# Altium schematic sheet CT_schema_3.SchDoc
size 590 x 495 mm
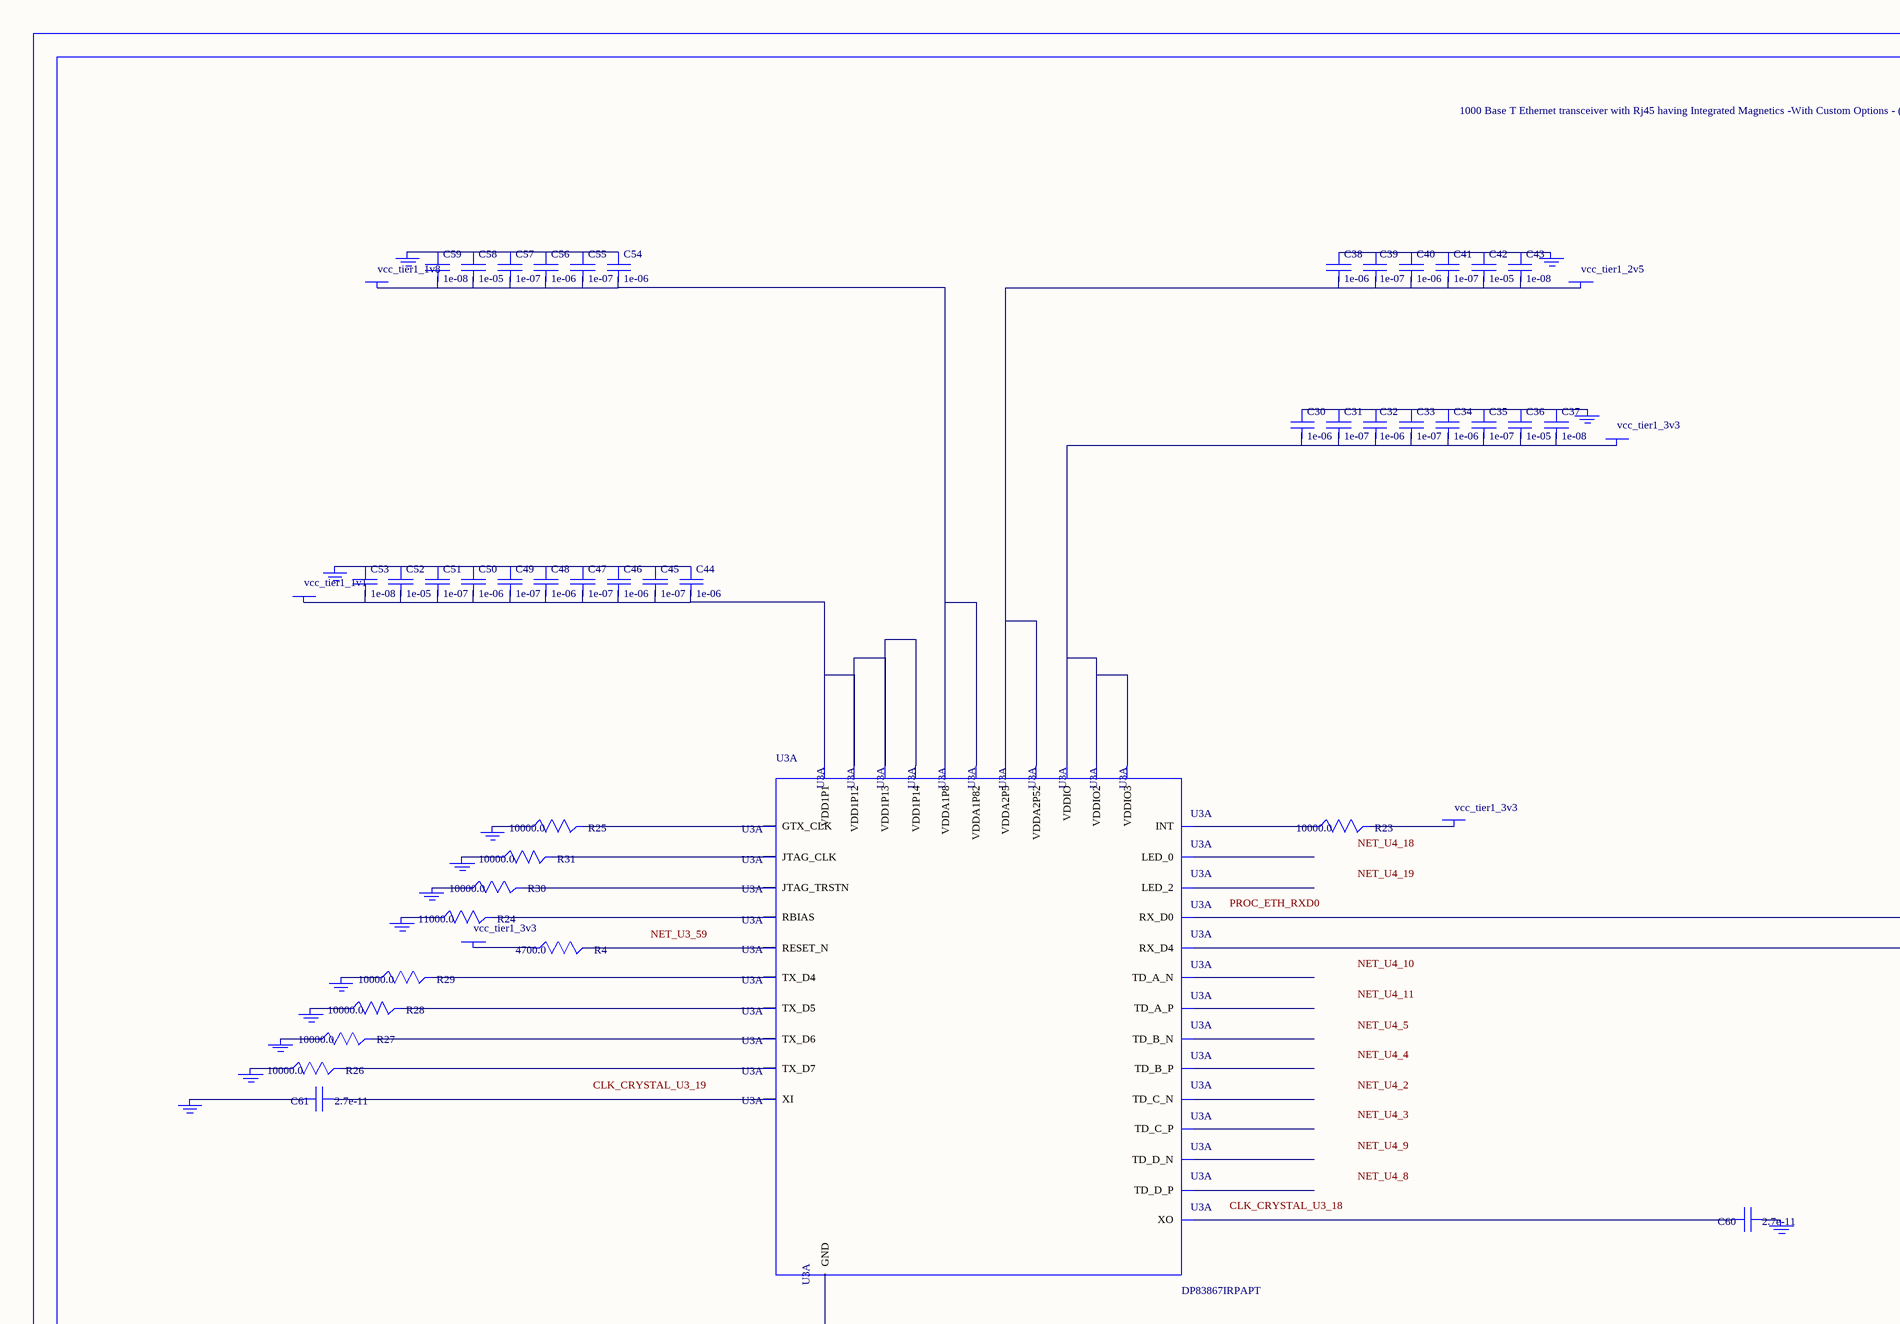
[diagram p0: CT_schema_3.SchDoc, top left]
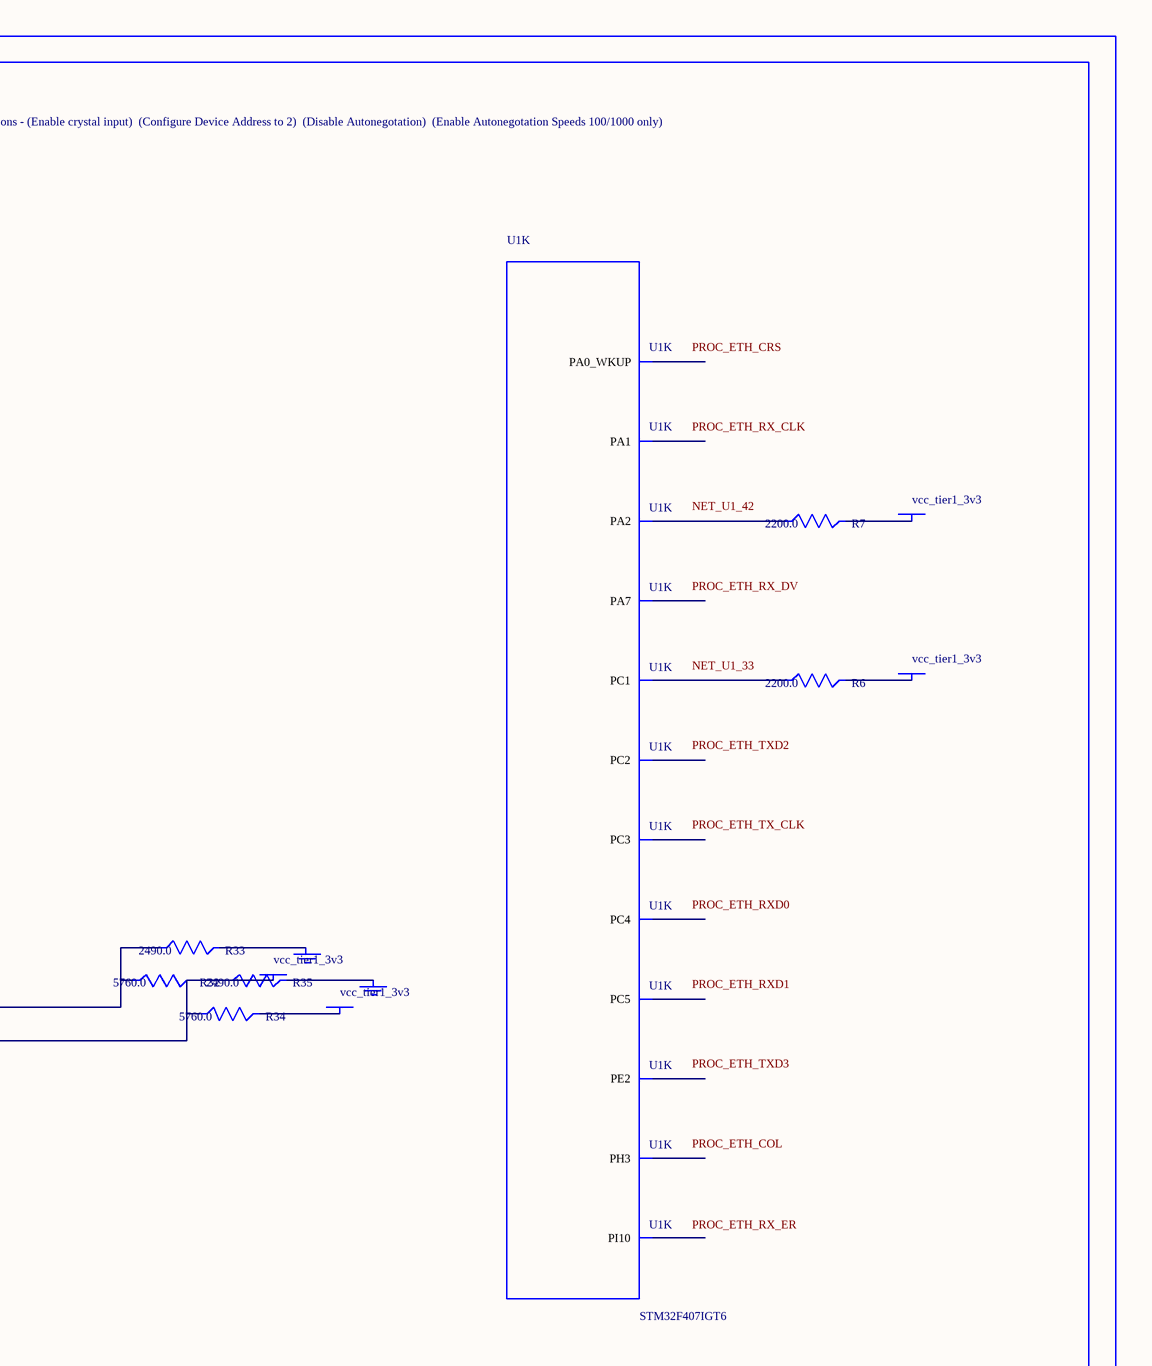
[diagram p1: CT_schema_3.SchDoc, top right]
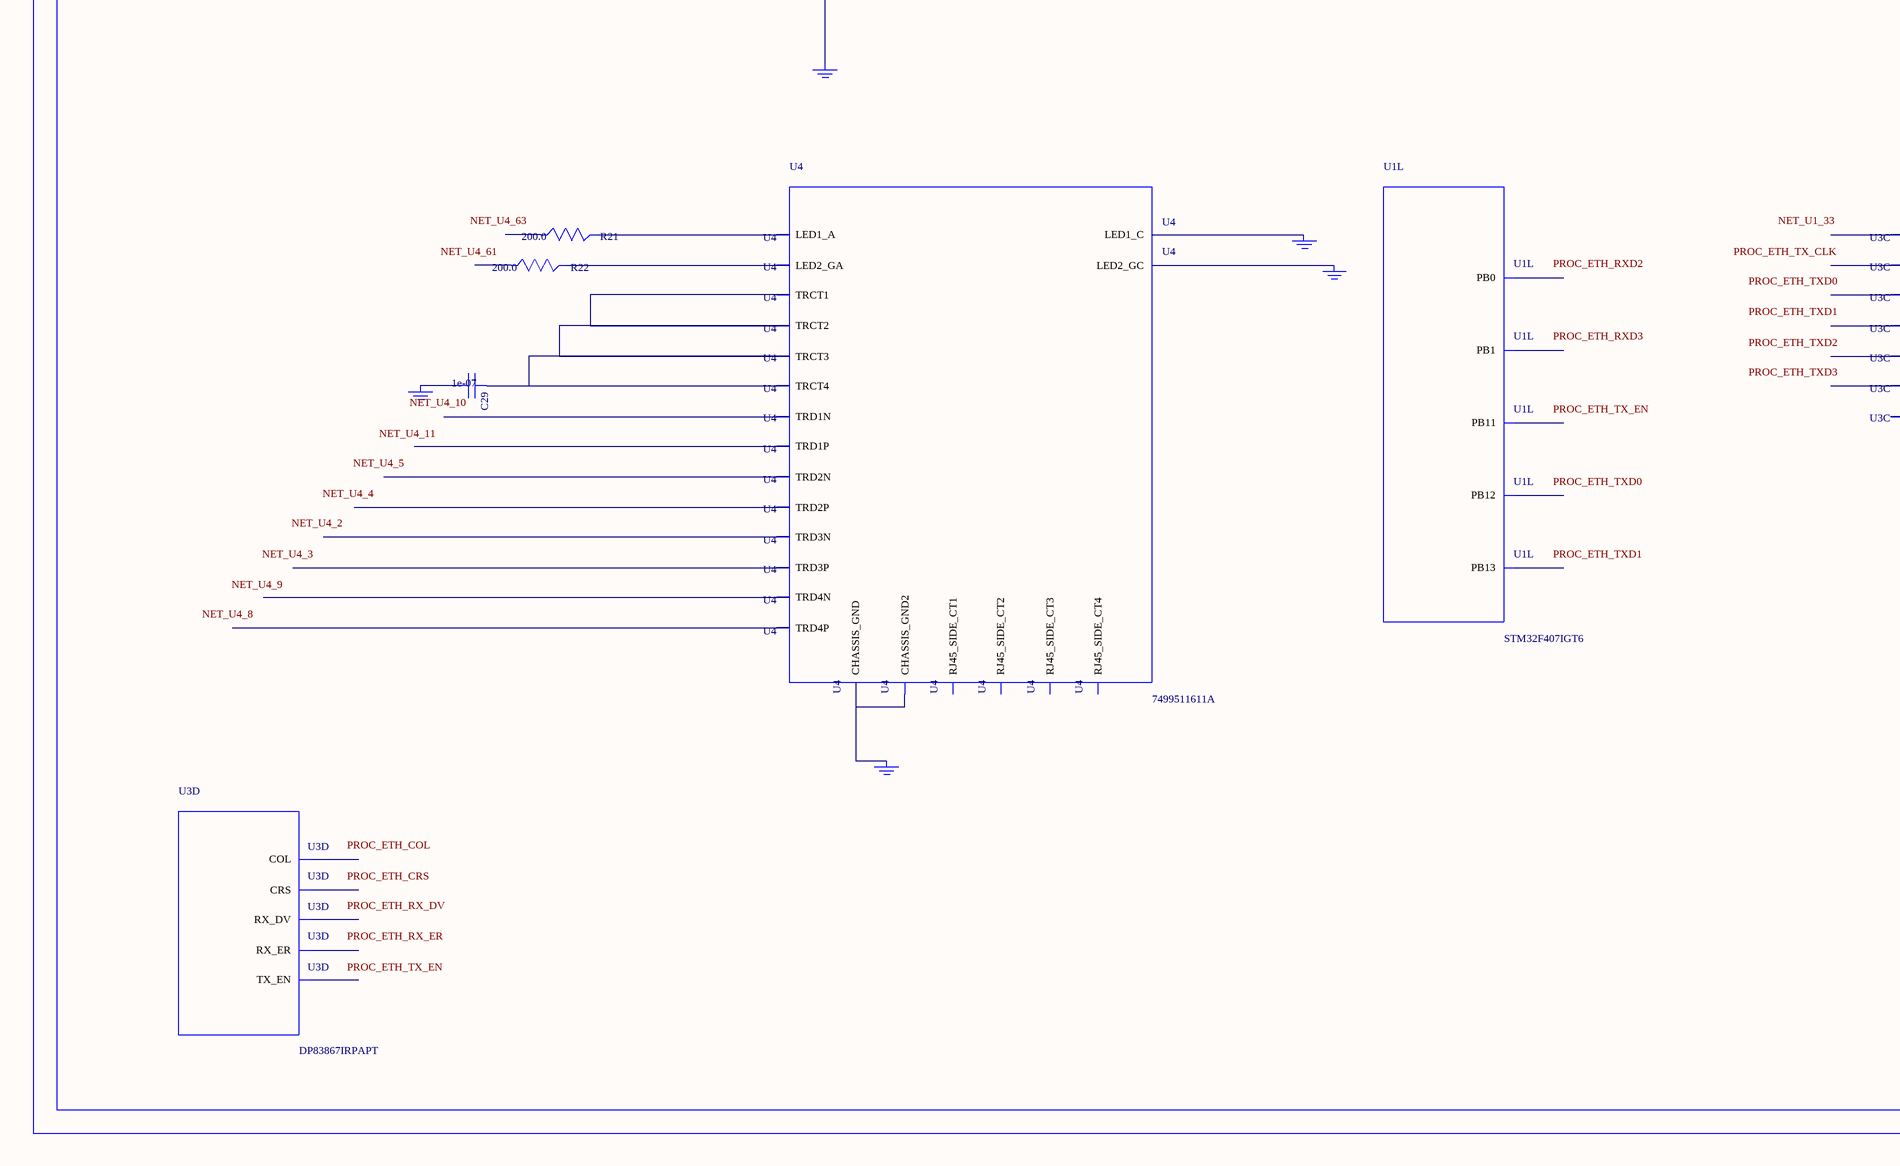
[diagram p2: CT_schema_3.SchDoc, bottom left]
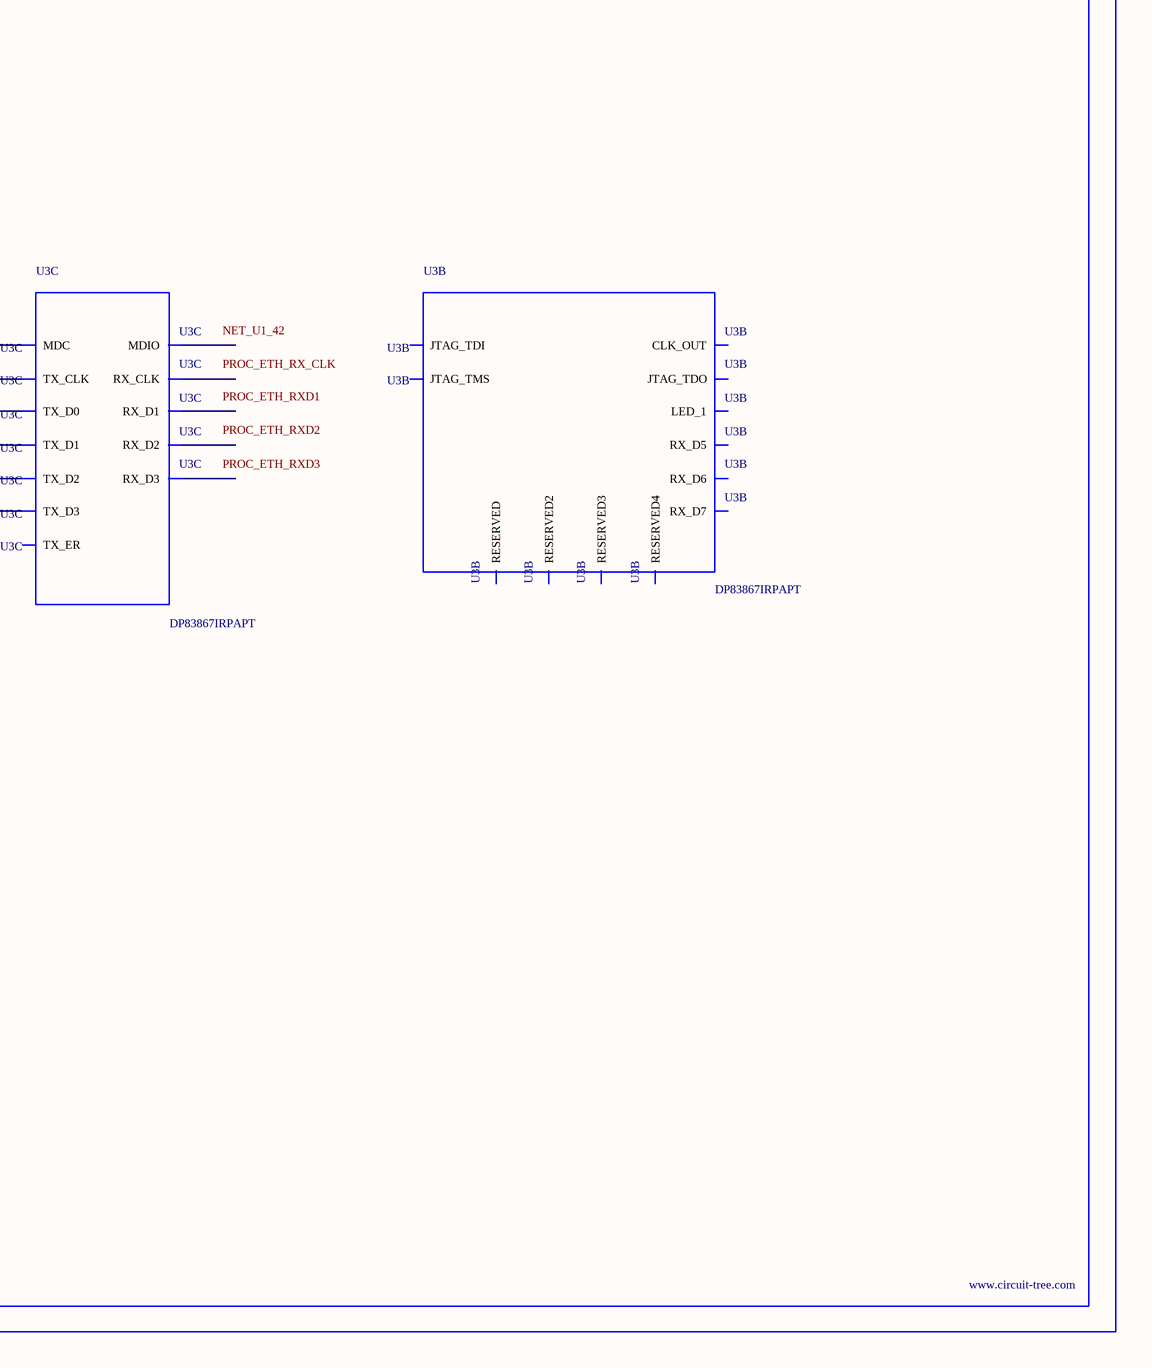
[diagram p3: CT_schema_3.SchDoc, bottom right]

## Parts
BORDER2  (no value)
C29  1e-07  [C0402]
C30  1e-06  [C0603]
C31  1e-07  [C0402]
C32  1e-06  [C0603]
C33  1e-07  [C0402]
C34  1e-06  [C0603]
C35  1e-07  [C0402]
C36  1e-05  [C0805]
C37  1e-08  [C0402]
C38  1e-06  [C0603]
C39  1e-07  [C0402]
C40  1e-06  [C0603]
C41  1e-07  [C0402]
C42  1e-05  [C0805]
C43  1e-08  [C0402]
C44  1e-06  [C0603]
C45  1e-07  [C0402]
C46  1e-06  [C0603]
C47  1e-07  [C0402]
C48  1e-06  [C0603]
C49  1e-07  [C0402]
C50  1e-06  [C0603]
C51  1e-07  [C0402]
C52  1e-05  [C0805]
C53  1e-08  [C0402]
C54  1e-06  [C0603]
C55  1e-07  [C0402]
C56  1e-06  [C0603]
C57  1e-07  [C0402]
C58  1e-05  [C0805]
C59  1e-08  [C0402]
C60  2.7e-11  [C0402]
C61  2.7e-11  [C0402]
GND_INSTANCE_2_0  (no value)
GND_INSTANCE_2_1  (no value)
GND_INSTANCE_2_2  (no value)
GND_INSTANCE_2_3  (no value)
GND_INSTANCE_2_4  (no value)
GND_INSTANCE_2_5  (no value)
GND_INSTANCE_2_6  (no value)
GND_INSTANCE_2_7  (no value)
GND_INSTANCE_2_8  (no value)
GND_INSTANCE_2_9  (no value)
GND_INSTANCE_2_10  (no value)
GND_INSTANCE_2_11  (no value)
GND_INSTANCE_2_12  (no value)
GND_INSTANCE_2_13  (no value)
GND_INSTANCE_2_14  (no value)
GND_INSTANCE_2_15  (no value)
GND_INSTANCE_2_16  (no value)
GND_INSTANCE_2_17  (no value)
GND_INSTANCE_2_18  (no value)
GND_INSTANCE_2_19  (no value)
GND_INSTANCE_2_20  (no value)
POWER_INSTANCE_2_0  vcc_tier1_2v5
POWER_INSTANCE_2_1  vcc_tier1_1v1
POWER_INSTANCE_2_2  vcc_tier1_1v8
POWER_INSTANCE_2_3  vcc_tier1_3v3
POWER_INSTANCE_2_4  vcc_tier1_3v3
POWER_INSTANCE_2_5  vcc_tier1_3v3
POWER_INSTANCE_2_6  vcc_tier1_3v3
POWER_INSTANCE_2_7  vcc_tier1_3v3
POWER_INSTANCE_2_8  vcc_tier1_3v3
POWER_INSTANCE_2_9  vcc_tier1_3v3
R4  4700.0  [R0603]
R6  2200.0  [R0603]
R7  2200.0  [R0603]
R21  200.0  [R0603]
R22  200.0  [R0603]
R23  10000.0  [R0603]
R24  11000.0  [R0603]
R25  10000.0  [R0603]
R26  10000.0  [R0603]
R27  10000.0  [R0603]
R28  10000.0  [R0603]
R29  10000.0  [R0603]
R30  10000.0  [R0603]
R31  10000.0  [R0603]
R32  5760.0  [R0603]
R33  2490.0  [R0603]
R34  5760.0  [R0603]
R35  2490.0  [R0603]
U1  STM32F407IGT6  [LQFP176]  (parts K,L of 14)
U3  DP83867IRPAPT  [HTQFP-64-EXP]  (parts A,B,C,D of 4)
U4  7499511611A  [7499511611A]

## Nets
NetC29_1: C29.1 U4.1(TRCT3) U4.6(TRCT2) U4.7(TRCT4) U4.12(TRCT1)
NetC29_2: C29.2 GND_INSTANCE_2_17.0(GND)
NetC30_1: C30.1 C31.1 C32.1 C33.1 C34.1 C35.1 C36.1 C37.1 GND_INSTANCE_2_6.0(GND)
NetC30_2: C30.2 C31.2 C32.2 C33.2 C34.2 C35.2 C36.2 C37.2 POWER_INSTANCE_2_3.0(PWR) U3.23(VDDIO) U3.41(VDDIO2) U3.57(VDDIO3)
NetC38_1: C38.1 C39.1 C40.1 C41.1 C42.1 C43.1 GND_INSTANCE_2_0.0(GND)
NetC38_2: C38.2 C39.2 C40.2 C41.2 C42.2 C43.2 POWER_INSTANCE_2_0.0(PWR) U3.4(VDDA2P5) U3.12(VDDA2P52)
NetC44_1: C44.1 C45.1 C46.1 C47.1 C48.1 C49.1 C50.1 C51.1 C52.1 C53.1 GND_INSTANCE_2_1.0(GND)
NetC44_2: C44.2 C45.2 C46.2 C47.2 C48.2 C49.2 C50.2 C51.2 C52.2 C53.2 POWER_INSTANCE_2_1.0(PWR) U3.8(VDD1P1) U3.29(VDD1P12) U3.42(VDD1P13) U3.58(VDD1P14)
NetC54_1: C54.1 C55.1 C56.1 C57.1 C58.1 C59.1 GND_INSTANCE_2_3.0(GND)
NetC54_2: C54.2 C55.2 C56.2 C57.2 C58.2 C59.2 POWER_INSTANCE_2_2.0(PWR) U3.17(VDDA1P8) U3.64(VDDA1P82)
NetC60_1: C60.1 GND_INSTANCE_2_4.0(GND)
NetC60_2: C60.2 U3.18(XO)
NetC61_1: C61.1 U3.19(XI)
NetC61_2: C61.2 GND_INSTANCE_2_5.0(GND)
NetGND_INSTANCE_2_2_0: GND_INSTANCE_2_2.0(GND) R24.1
NetGND_INSTANCE_2_7_0: GND_INSTANCE_2_7.0(GND) R30.1
NetGND_INSTANCE_2_8_0: GND_INSTANCE_2_8.0(GND) R31.1
NetGND_INSTANCE_2_9_0: GND_INSTANCE_2_9.0(GND) R26.1
NetGND_INSTANCE_2_10_0: GND_INSTANCE_2_10.0(GND) R27.1
NetGND_INSTANCE_2_11_0: GND_INSTANCE_2_11.0(GND) R28.1
NetGND_INSTANCE_2_12_0: GND_INSTANCE_2_12.0(GND) R29.1
NetGND_INSTANCE_2_13_0: GND_INSTANCE_2_13.0(GND) R25.1
NetGND_INSTANCE_2_14_0: GND_INSTANCE_2_14.0(GND) R33.2
NetGND_INSTANCE_2_15_0: GND_INSTANCE_2_15.0(GND) R35.2
NetGND_INSTANCE_2_16_0: GND_INSTANCE_2_16.0(GND) U3.EXP(GND)
NetGND_INSTANCE_2_18_0: GND_INSTANCE_2_18.0(GND) U4.17(LED1_C)
NetGND_INSTANCE_2_19_0: GND_INSTANCE_2_19.0(GND) U4.20(LED2_GC)
NetGND_INSTANCE_2_20_0: GND_INSTANCE_2_20.0(GND) U4.Z1(CHASSIS_GND) U4.Z2(CHASSIS_GND2)
NetPOWER_INSTANCE_2_4_0: POWER_INSTANCE_2_4.0(PWR) R32.2 R34.1 R35.1 U3.48(RX_D4)
NetPOWER_INSTANCE_2_5_0: POWER_INSTANCE_2_5.0(PWR) R34.2
NetPOWER_INSTANCE_2_6_0: POWER_INSTANCE_2_6.0(PWR) R23.2
NetPOWER_INSTANCE_2_7_0: POWER_INSTANCE_2_7.0(PWR) R4.1
NetPOWER_INSTANCE_2_8_0: POWER_INSTANCE_2_8.0(PWR) R6.2
NetPOWER_INSTANCE_2_9_0: POWER_INSTANCE_2_9.0(PWR) R7.2
NetR4_2: R4.2 U3.59(RESET_N)
NetR6_1: R6.1 U1.33(PC1)
NetR7_1: R7.1 U1.42(PA2)
NetR21_2: R21.2 U4.18(LED1_A)
NetR22_2: R22.2 U4.19(LED2_GA)
NetR23_1: R23.1 U3.60(INT)
NetR24_2: R24.2 U3.15(RBIAS)
NetR25_2: R25.2 U3.40(GTX_CLK)
NetR26_2: R26.2 U3.31(TX_D7)
NetR27_2: R27.2 U3.32(TX_D6)
NetR28_2: R28.2 U3.33(TX_D5)
NetR29_2: R29.2 U3.34(TX_D4)
NetR30_2: R30.2 U3.24(JTAG_TRSTN)
NetR31_2: R31.2 U3.25(JTAG_CLK)
NetR32_1: R32.1 R33.1 U3.44(RX_D0)

Not connected (* = marked no-connect by the designer): R21 1; R22 1; U1 1(PE2) 12(PI10) 34(PC2) 35(PC3) 40(PA0_WKUP) 41(PA1) 44(PH3) 53(PA7) 54(PC4) 55(PC5) 56(PB0) 57(PB1) 80(PB11) 92(PB12) 93(PB13); U3 1(RESERVED) 2(TD_A_P) 3(TD_A_N) 5(TD_B_P) 6(TD_B_N) 7(RESERVED2) 9(RESERVED3) 10(TD_C_P) 11(TD_C_N) 13(TD_D_P) 14(TD_D_N) 16(RESERVED4) 20(MDC) 21(MDIO) 22(CLK_OUT) 26(JTAG_TDO) 27(JTAG_TMS) 28(JTAG_TDI) 30(TX_CLK) 35(TX_D3) 36(TX_D2) 37(TX_D1) 38(TX_D0) 39(TX_ER) 43(RX_CLK) 45(RX_D1) 46(RX_D2) 47(RX_D3) 49(RX_D5) 50(RX_D6) 51(RX_D7) 52(TX_EN) 53(RX_DV) 54(RX_ER) 55(COL) 56(CRS) 61(LED_2) 62(LED_1) 63(LED_0); U4 2(TRD3N) 3(TRD3P) 4(TRD2P) 5(TRD2N) 8(TRD4P) 9(TRD4N) 10(TRD1N) 11(TRD1P) 13(RJ45_SIDE_CT1) 14(RJ45_SIDE_CT2) 15(RJ45_SIDE_CT3) 16(RJ45_SIDE_CT4)

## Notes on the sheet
- Labels drawn without touching a wire or pin: CLK_CRYSTAL_U3_18, CLK_CRYSTAL_U3_19, NET_U1_33, NET_U1_42, NET_U3_59, NET_U4_2, NET_U4_3, NET_U4_4, NET_U4_5, NET_U4_8, NET_U4_9, NET_U4_10, NET_U4_11, NET_U4_18, NET_U4_19, NET_U4_61, NET_U4_63, PROC_ETH_COL, PROC_ETH_CRS, PROC_ETH_RX_CLK, PROC_ETH_RX_DV, PROC_ETH_RX_ER, PROC_ETH_RXD0, PROC_ETH_RXD1, PROC_ETH_RXD2, PROC_ETH_RXD3, PROC_ETH_TX_CLK, PROC_ETH_TX_EN, PROC_ETH_TXD0, PROC_ETH_TXD1, PROC_ETH_TXD2, PROC_ETH_TXD3

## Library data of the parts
BORDER2 = BORDER_PAGE2
C29 C31 C33 C35 C39 C41 C45 C47 C49 C51 C55 C57 = C0402C104K3RACTU
C30 C32 C34 C38 C40 C44 C46 C48 C50 C54 C56 = C0603C105K3RACTU
C36 C42 C52 C58 = C0805C106K8RACTU
C37 C43 C53 C59 = C0402C103K3RAC
C60 C61 = C0402C270K3RAC
GND_INSTANCE_2_0-GND_INSTANCE_2_20 = GND
POWER_INSTANCE_2_0-POWER_INSTANCE_2_9 = PWR
R4 = RC0603JR-074K7L
R6 R7 = RC0603JR-072K2L
R21 R22 = RC0603JR-07200RL
R23 R25-R31 = RC0603JR-0710KL
R24 = RC0603JR-0711KL
R32 R34 = ERJ-3EKF5760V
R33 R35 = ERA-3AED2490V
